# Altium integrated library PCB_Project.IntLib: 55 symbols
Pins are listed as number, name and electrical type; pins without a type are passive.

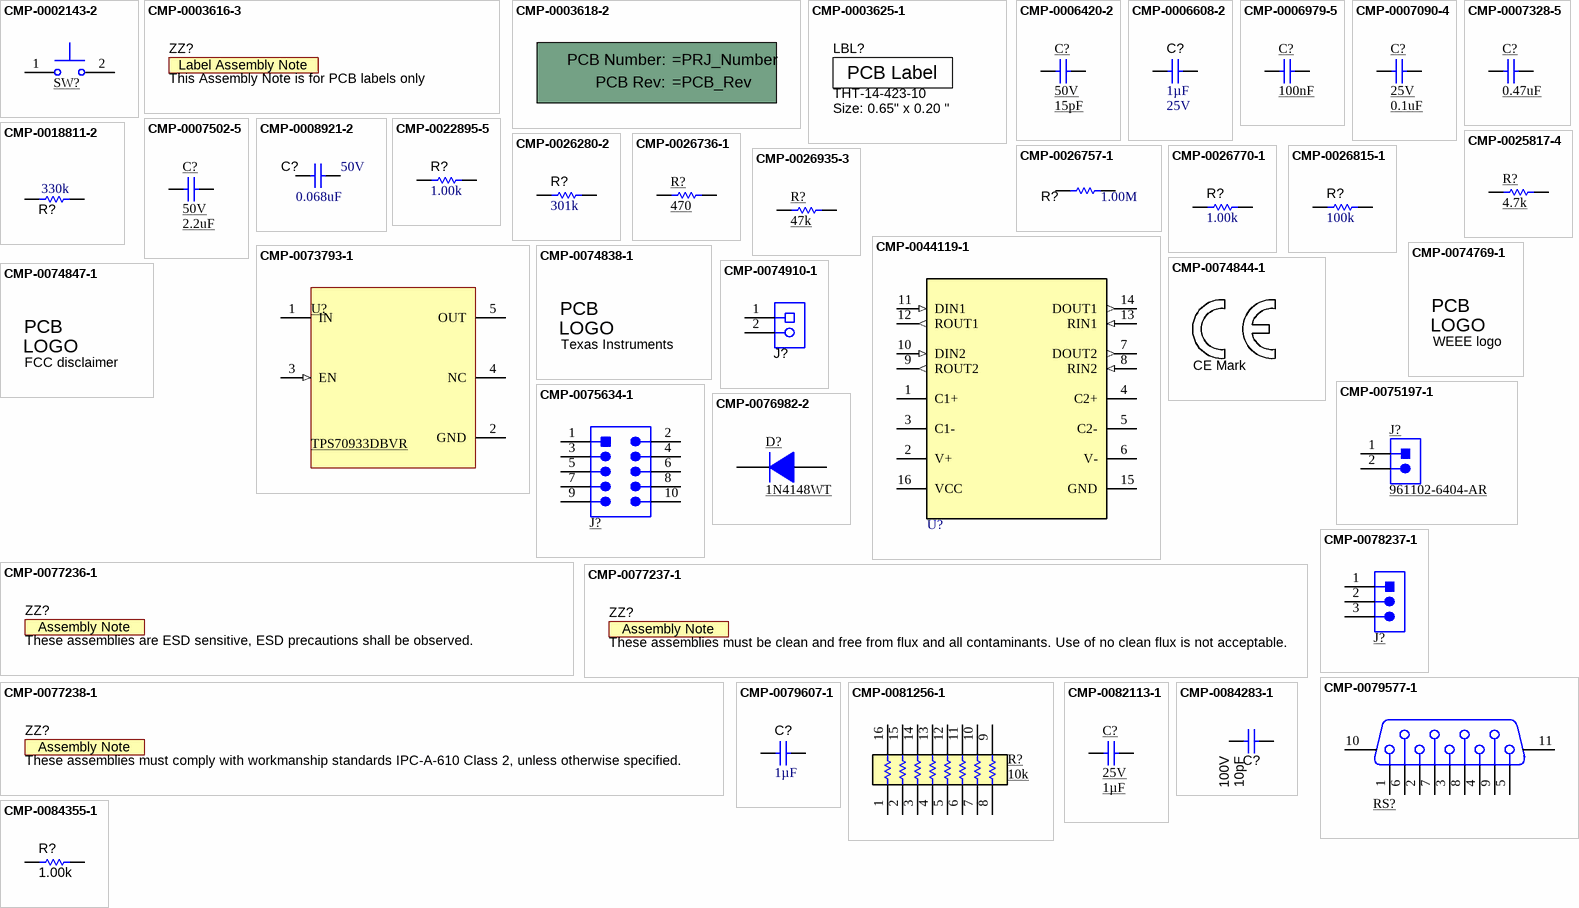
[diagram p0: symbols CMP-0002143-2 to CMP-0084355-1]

## CMP-0002143-2
designator SW?, comment TL1015AF160QG  (value not drawn)
Switch, Tactile, SPST-NO, 0.05A, 12V, SMT; Manufacturer: E-Switch; CurrentRating_mA: 50A; PositionCount: 1; SwitchFunction: Off-Mom
footprint SW_TL1015AF160QG (E-Switch)
pins: 1, 2

## CMP-0003616-3
designator ZZ?, comment This Assembly Note is for PCB labels only  (no BOM)
Key: AssemblyNoteLabel
footprint AssemblyNoteLabel (Assembly Note for PCB Labels)

## CMP-0003618-2
designator !PCB?, comment Printed Circuit Board  (value not drawn)  (mechanical)
Manufacturer: Any; CompType: PCB
1 alternate drawing of the same symbol

## CMP-0003625-1
designator LBL?, comment THT-14-423-10  Note: Size: 0.65" x 0.20 "
Thermal Transfer Printable Labels, 0.650" W x 0.200" H - 10,000 per roll; Manufacturer: Brady; CompType: Label
footprint Label_650x200 (Thermal Transfer Label)

## CMP-0006420-2
designator C?, comment VDC_V: 50V  ValueDisplayed: 15pF  (hidden comment: GRM1555C1H150JA01D)
CAP, CERM, 15 pF, 50 V, +/- 5%, C0G/NP0, 0402; Manufacturer: MuRata; TaMin_C: -55°C; Polarized: N; SizeAreaWB_mm2: 3; Value1: Unknown; U/M: EA; Value: 15pF; TaMax_C: 125°C; SizeZ_mm: 0.6; SizeX_mm: 1; SizeY_mm: 0.5; Cap_Case: 0402; CompType: Capacitor; AEC Category: Q200
footprint 0402 (0402 from SM-752 data)
footprint 0402S (Based on C0402S footprint from PADS legacy)
footprint 0402L (0402 from SM-752 data)
footprint 0402M (0402 from SM-752 data)
pins: 1, 2

## CMP-0006608-2
designator C?, comment Cap_F: 1µF  VDC_V: 25V  (hidden comment: GRM155R61E105KA12D)
CAP, CERM, 1 uF, 25 V, +/- 10%, X5R, 0402; Manufacturer: MuRata; TaMin_C: -55°C; Polarized: N; SizeAreaWB_mm2: 3; U/M: EA; Value: 1uF; TaMax_C: 85°C; SizeZ_mm: 0.6; SizeX_mm: 1; SizeY_mm: 0.5; Cap_Case: 0402; CompType: Capacitor; AEC Category: Q200; Value1: Unknown
footprint 0402 (0402 from SM-752 data)
footprint 0402S (Based on C0402S footprint from PADS legacy)
footprint 0402L (0402 from SM-752 data)
footprint 0402M (0402 from SM-752 data)
pins: 1, 2

## CMP-0006979-5
designator C?, comment Cap_F: 100nF  (hidden comment: C0603X104K3RACTU)
CAP, CERM, 0.1 uF, 25 V, +/- 10%, X7R, 0603; Manufacturer: Kemet; TaMin_C: -55°C; Polarized: N; SizeAreaWB_mm2: 4.68; Value1: Unknown; U/M: EA; Value: 0.1uF; TaMax_C: 125°C; SizeZ_mm: 1; SizeX_mm: 1.6; SizeY_mm: 0.8; Cap_Case: 0603; Value2: 25V; SizeArea_mm2: 1.28; CompType: Capacitor; AEC Category: Q200
footprint 0603 (0603 from SM-752 data)
footprint 0603_HV (Ernesto recommended land pattern.  26 mil between pads.)
footprint 0603L (0603 from SM-752 data)
footprint 0603S
footprint 0603M (0603 from SM-752 data)
pins: 1, 2

## CMP-0007090-4
designator C?, comment VDC_V: 25V  ValueDisplayed: 0.1uF  (hidden comment: CGA3E2X8R1E104K080AA)
CAP, CERM, 0.1 uF, 25 V, +/- 10%, X8R, AEC-Q200 Grade 0, 0603; Manufacturer: TDK; TaMin_C: -55°C; Polarized: N; SizeAreaWB_mm2: 4.68; Value1: Unknown; U/M: EA; Value: 0.1uF; TaMax_C: 150°C; SizeZ_mm: 1; SizeX_mm: 1.6; SizeY_mm: 0.8; Cap_Case: 0603; SizeArea_mm2: 1.28; CompType: Capacitor; AEC Qualified: Y; Cap_F: 100nF; AEC Grade: 0; AEC Category: Q200
footprint 0603 (0603 from SM-752 data)
footprint 0603_HV (Ernesto recommended land pattern.  26 mil between pads.)
footprint 0603L (0603 from SM-752 data)
footprint 0603S
footprint 0603M (0603 from SM-752 data)
pins: 1, 2

## CMP-0007328-5
designator C?, comment ValueDisplayed: 0.47uF  (hidden comment: GRM188R61A474KA61D)
CAP, CERM, 0.47 uF, 10 V, +/- 10%, X5R, 0603; Manufacturer: MuRata; TaMin_C: -55°C; Polarized: N; SizeAreaWB_mm2: 4.68; Value1: Unknown; U/M: EA; Value: 0.47uF; TaMax_C: 85°C; SizeZ_mm: 1; SizeX_mm: 1.6; SizeY_mm: 0.8; Cap_Case: 0603; Value2: 10V; SizeArea_mm2: 1.28; CompType: Capacitor; Cap_F: 470nF; AEC Category: Q200
footprint 0603 (0603 from SM-752 data)
footprint 0603_HV (Ernesto recommended land pattern.  26 mil between pads.)
footprint 0603L (0603 from SM-752 data)
footprint 0603S
footprint 0603M (0603 from SM-752 data)
pins: 1, 2

## CMP-0007502-5
designator C?, comment VDC_V: 50V  ValueDisplayed: 2.2uF  (hidden comment: GRT188R61H225KE13D)
CAP, CERM, 2.2 uF, 50 V, +/- 10%, X5R, AEC-Q200 Grade 3, 0603; Manufacturer: MuRata; TaMin_C: -55°C; Polarized: N; SizeAreaWB_mm2: 4.68; Value1: Unknown; U/M: EA; Value: 2.2uF; TaMax_C: 85°C; SizeZ_mm: 1; SizeX_mm: 1.6; SizeY_mm: 0.8; Cap_Case: 0603; SizeArea_mm2: 1.28; CompType: Capacitor; AEC Qualified: Y; Cap_F: 2.2µF; AEC Grade: 3; AEC Category: Q200
footprint 0603 (0603 from SM-752 data)
footprint 0603_HV (Ernesto recommended land pattern.  26 mil between pads.)
footprint 0603L (0603 from SM-752 data)
footprint 0603S
footprint 0603M (0603 from SM-752 data)
pins: 1, 2

## CMP-0008921-2
designator C?, comment VDC_V: 50V  ValueDisplayed: 0.068uF  (hidden comment: GRM31C5C1H683JA01L)
CAP, CERM, 0.068 uF, 50 V, +/- 5%, C0G/NP0, 1206; Manufacturer: MuRata; TaMin_C: -55°C; ESR_ohm: 10m; Polarized: N; SizeAreaWB_mm2: 10.92; Value1: 0.01 ohm; U/M: EA; TaMax_C: 125°C; SizeZ_mm: 1.8; SizeX_mm: 3.2; SizeY_mm: 1.6; Cap_Case: 1206; SizeArea_mm2: 5.12; CompType: Capacitor; Cap_F: 68nF; IRMS_A: 900mA; AEC Category: Q200
footprint 1206_180
footprint 1206_180L (1206_180)
footprint 1206_180M (1206_180)
pins: 1, 2

## CMP-0018811-2
designator R?, comment ValueDisplayed: 330k  (hidden comment: TNPV1206330KBEEN)
RES, 330 k, 0.1%, 1 W, 1206; Manufacturer: Vishay Draloric; Power_W: 1W; TempCo: 25 ppm/C; U/M: EA; Value: 330k; SizeX_mm: 3.2; SizeY_mm: 1.6; SizeZ_mm: 0.65; SizeArea_mm2: 5.12; CompType: Resistor; AEC Qualified: N; VDC_V: 700V; AEC Category: Q200
footprint TNPV1206 (VISHAY)
pins: 1, 2

## CMP-0022895-5
designator R?, comment ValueDisplayed: 1.00k  (hidden comment: RC0603FR-071KL)
RES, 1.00 k, 1%, 0.1 W, 0603; Manufacturer: Yageo; Power_W: 100mW; TempCo: 100 ppm/C; Value_Code: 1k00; Value: 1.00k; EIA_Code: E96; Res_ohm: 1k; SizeX_mm: 1.6; SizeY_mm: 0.8; SizeZ_mm: 1; Value2: 0.1W; SizeArea_mm2: 1.28; CompType: Resistor; AEC Qualified: N; VDC_V: 75V; AEC Category: Q200; SizeAreaWB_mm2: 4.68
footprint 0603 (0603 from SM-752 data)
footprint 0603_HV (Ernesto recommended land pattern.  26 mil between pads.)
footprint 0603L (0603 from SM-752 data)
footprint 0603S
footprint 0603M (0603 from SM-752 data)
pins: 1, 2

## CMP-0025817-4
designator R?, comment ValueDisplayed: 4.7k  (hidden comment: CRCW06034K70JNEA)
RES, 4.7 k, 5%, 0.1 W, AEC-Q200 Grade 0, 0603; Manufacturer: Vishay-Dale; Power_W: 100mW; TempCo: 200 ppm/C; Value_Code: 4k70; Value: 4.7k; EIA_Code: E24; SizeX_mm: 1.6; SizeY_mm: 0.8; SizeZ_mm: 1; Value2: 0.1W; SizeArea_mm2: 1.28; CompType: Resistor; AEC Qualified: Y; VDC_V: 75V; AEC Category: Q200; AEC Grade: 0
footprint 0603 (0603 from SM-752 data)
footprint 0603_HV (Ernesto recommended land pattern.  26 mil between pads.)
footprint 0603L (0603 from SM-752 data)
footprint 0603S
footprint 0603M (0603 from SM-752 data)
pins: 1, 2

## CMP-0026280-2
designator R?, comment ValueDisplayed: 301k  (hidden comment: CRCW0402301KFKED)
RES, 301 k, 1%, 0.063 W, AEC-Q200 Grade 0, 0402; Manufacturer: Vishay-Dale; Power_W: 63mW; TempCo: 100 ppm/C; Value: 301k; EIA_Code: E96; SizeX_mm: 1; SizeY_mm: 0.5; SizeZ_mm: 0.6; Value2: 0.063W; CompType: Resistor; AEC Qualified: Y; VDC_V: 50V; AEC Category: Q200; AEC Grade: 0
footprint 0402 (0402 from SM-752 data)
footprint 0402S (Based on C0402S footprint from PADS legacy)
footprint 0402L (0402 from SM-752 data)
footprint 0402M (0402 from SM-752 data)
pins: 1, 2

## CMP-0026736-1
designator R?, comment ValueDisplayed: 470  (hidden comment: RC0402FR-07470RL)
RES, 470, 1%, 0.063 W, 0402; Manufacturer: Yageo America; Power_W: 63mW; TempCo: 100 ppm/C; Value_Code: 470R; U/M: EA; Value: 470; SizeX_mm: 1; SizeY_mm: 0.5; SizeZ_mm: 0.6; Value2: 0.063W; CompType: Resistor; AEC Qualified: N; VDC_V: 50V; AEC Category: Q200
footprint 0402 (0402 from SM-752 data)
footprint 0402S (Based on C0402S footprint from PADS legacy)
footprint 0402L (0402 from SM-752 data)
footprint 0402M (0402 from SM-752 data)
pins: 1, 2

## CMP-0026757-1
designator R?, comment ValueDisplayed: 1.00M  (hidden comment: RMCF0402FT1M00)
RES, 1.00 M, 1%, 0.063 W, AEC-Q200 Grade 0, 0402; Manufacturer: Stackpole Electronics Inc; Power_W: 63mW; TempCo: 100 ppm/C; Value_Code: 1M00; Value: 1.00Meg; EIA_Code: E96; Res_ohm: 1M; SizeX_mm: 1; SizeY_mm: 0.5; SizeZ_mm: 0.6; Value2: 0.063W; CompType: Resistor; AEC Qualified: Y; VDC_V: 50V; AEC Category: Q200; AEC Grade: 0; U/M: EA
footprint 0402 (0402 from SM-752 data)
footprint 0402S (Based on C0402S footprint from PADS legacy)
footprint 0402L (0402 from SM-752 data)
footprint 0402M (0402 from SM-752 data)
pins: 1, 2

## CMP-0026770-1
designator R?, comment ValueDisplayed: 1.00k  (hidden comment: ERA-2AEB102X)
RES, 1.00 k, 0.1%, 0.063 W, 0402; Manufacturer: Panasonic; Power_W: 63mW; TempCo: 25 ppm/C; Value_Code: 1k00; Value: 1.00k; EIA_Code: E192; Res_ohm: 1k; SizeX_mm: 1; SizeY_mm: 0.5; SizeZ_mm: 0.6; Value2: 0.063W; CompType: Resistor; AEC Category: Q200; VDC_V: 50V; U/M: EA
footprint 0402 (0402 from SM-752 data)
footprint 0402S (Based on C0402S footprint from PADS legacy)
footprint 0402L (0402 from SM-752 data)
footprint 0402M (0402 from SM-752 data)
pins: 1, 2

## CMP-0026815-1
designator R?, comment ValueDisplayed: 100k  (hidden comment: RG1005P-104-B-T5)
RES, 100 k, 0.1%, 0.063 W, 0402; Manufacturer: Susumu Co Ltd; Power_W: 63mW; TempCo: 25 ppm/C; Value: 100k; EIA_Code: E192; SizeX_mm: 1; SizeY_mm: 0.5; SizeZ_mm: 0.6; Value2: 0.063W; CompType: Resistor; AEC Category: Q200; U/M: EA
footprint 0402 (0402 from SM-752 data)
footprint 0402S (Based on C0402S footprint from PADS legacy)
footprint 0402L (0402 from SM-752 data)
footprint 0402M (0402 from SM-752 data)
pins: 1, 2

## CMP-0026935-3
designator R?, comment ValueDisplayed: 47k  (hidden comment: CRCW040247K0JNED)
RES, 47 k, 5%, 0.063 W, AEC-Q200 Grade 0, 0402; Manufacturer: Vishay-Dale; Power_W: 63mW; TempCo: 200 ppm/C; Value_Code: 47k0; Value: 47k; EIA_Code: E24; SizeX_mm: 1; SizeY_mm: 0.5; SizeZ_mm: 0.6; Value2: 0.063W; CompType: Resistor; AEC Qualified: Y; VDC_V: 50V; AEC Category: Q200; AEC Grade: 0
footprint 0402 (0402 from SM-752 data)
footprint 0402S (Based on C0402S footprint from PADS legacy)
footprint 0402L (0402 from SM-752 data)
footprint 0402M (0402 from SM-752 data)
pins: 1, 2

## CMP-0044119-1
designator U?, comment TRS3232EIDBR  (value not drawn)
3-V to 5.5-V Multichannel RS-232 Line Driver / Receiver with ±15-kV IEC ESD Protection, -40 to 85 degC, 16-Pin SSOP (DB), Green (RoHS & no Sb/Br); ESD HBM(kV): +/-15; Receivers Per Package: 2; Single Supply: TRUE; ICC(Max)(mA): 1; Supply Voltage(s)(V): 3.3 or 5.0
footprint DB0016A_L (SOP, 16-Leads, Body 6.2x5.3mm, Pitch 0.65mm, IPC High Density)
footprint DB0016A_M (SOP, 16-Leads, Body 6.2x5.3mm, Pitch 0.65mm, IPC Low Density)
footprint DB0016A_N (SOP, 16-Leads, Body 6.2x5.3mm, Pitch 0.65mm, IPC Medium Density)
pins: 1 C1+, 2 V+ (power), 3 C1-, 4 C2+, 5 C2-, 6 V- (power), 7 DOUT2 (out), 8 RIN2 (in), 9 ROUT2 (out), 10 DIN2 (in), 11 DIN1 (in), 12 ROUT1 (out), 13 RIN1 (in), 14 DOUT1 (out), 15 GND (power), 16 VCC (power)

## CMP-0073793-1
designator U?, comment TPS70933DBVR
150-mA, 30-V, Ultra-Low IQ, Wide Input Low-Dropout Regulator with Reverse Current Protection, DBV0005A (SOT-23-5); Alternate PartNumber: TPS70933DBVT; Alternate Manufacturer: Texas Instruments; Green_Lifecycle: Active; SizeAreaWB_mm2: 14.82; Green_REACh: Passed; U/M: EA; SizeZ_mm: 1.45; SizeX_mm: 2.8; SizeY_mm: 2.9; SizeArea_mm2: 8.12; CompType: IC
footprint DBV0005A_N (SOT23, 5-Leads, Body 2.9x1.6mm, Pitch 0.95mm, Lead Span 2.8mm, IPC Medium Density)
footprint DBV0005A_L (SOT23, 5-Leads, Body 2.9x1.6mm, Pitch 0.95mm, Lead Span 2.8mm, IPC High Density)
footprint DBV0005A_M (SOT23, 5-Leads, Body 2.9x1.6mm, Pitch 0.95mm, Lead Span 2.8mm, IPC Low Density)
pins: 1 IN (power) "Unregulated input to the device", 2 GND (power) "Ground", 3 EN (in) "Enable pin", 4 NC "No internal connection", 5 OUT (power) "Regulated output voltage."
1 alternate drawing of the same symbol

## CMP-0074769-1
designator Logo?, comment WEEE logo  (no BOM)
footprint WEEE_Minimum (WEEElie bin)

## CMP-0074838-1
designator Logo?, comment Texas Instruments  (no BOM)
Texas Instrument Corporate Signature; SymbolCreator: a0412235; Lib Reference: TI_Logo; Library Reference: Logo
footprint TI_Horizontal_Overlay_Medium
footprint TI_Horizontal_Overlay_Small
footprint TI_Stacked_SolderMask_Small
footprint TI_Stacked_SolderMask_Small_Vertical
footprint TI_Symbol_Overlay_Medium
footprint TI_Symbol_Overlay_Small
footprint TI_Symbol_SolderMask_Medium
footprint TI_Symbol_SolderMask_Small
footprint TI_Horizontal_SolderMask_Medium
footprint TI_Horizontal_SolderMask_Small
footprint TI_Stacked_Overlay_Medium
footprint TI_Stacked_Overlay_Medium_Vertical
footprint TI_Stacked_Overlay_Small
footprint TI_Stacked_Overlay_Small_Vertical
footprint TI_Stacked_SolderMask_Medium
footprint TI_Stacked_SolderMask_Medium_Vertical

## CMP-0074844-1
designator Logo?, comment CE Mark  (no BOM)
SymbolCreator: a0412235
footprint CE_Mark_5mm (Minimum text height for CE Mark)
footprint CE_Mark_10mm (Double the minimum text height for CE Mark)

## CMP-0074847-1
designator Logo?, comment FCC disclaimer  (no BOM)
FCC_disclaimer; Library Reference: Logo
footprint FCC_disclaimer
footprint FCC_disclaimer_stacked

## CMP-0074910-1
designator J?, comment ED120/2DS  (value not drawn)
Terminal Block, 5.08 mm, 2x1, Brass, TH; Manufacturer: On-Shore Technology; Cert_VDE: Y; CNHeader: False; Current_A: 15A; Green_Lifecycle: Not Set; Shrouded: N; Gender: Female; Green_REACh: Incomplete; Voltage_V: 300V; Row_Count: 1; Pitch_mm: 5.08; CT: True
footprint On-Shore_ED120_2DS (ONSHORE)
pins: 1, 2

## CMP-0075197-1
designator J?, comment 961102-6404-AR
Header, 2.54mm, 2x1, TH; Manufacturer: 3M; CNHeader: True; Current_A: 2A; Green_Lifecycle: Active; Shrouded: N; Gender: Male; Green_REACh: Passed; Voltage_V: 1kV; Row_Count: 1; Pitch_mm: 2.54; ContactFinish: Gold; CT: False; Cert_UL: Y
footprint 3M_961102-6404-AR (Header, 2.54mm, 2x1, TH)
pins: 1, 2
1 alternate drawing of the same symbol

## CMP-0075634-1
designator J?, comment FTSH-105-01-L-DV-K  (value not drawn)
Header(Shrouded), 1.27mm, 5x2, Gold, SMT; Manufacturer: Samtec; Pitch_mm: 1.27; Gender: Male; Cert_CSA: Y; Current_A: 3.3A; CT: False; Row_Count: 2
footprint Samtec_FTSH-105-01-x-DV-K (Header(Shrouded), 1.27mm, 5x2, SMT)
pins: 1, 2, 3, 4, 5, 6, 7, 8, 9, 10

## CMP-0076982-2
designator D?, comment 1N4148WT
Diode, Switching, 75 V, 0.3 A, SOD-523F; Manufacturer: Fairchild Semiconductor; TJmax_C: 150°C; AEC Category: Q101; SizeX_mm: 1.6; Value: 75V; Io_A: 300mA; Value1: 0.3A; Green_REACh: Incomplete; SizeZ_mm: 0.7; Green_Lifecycle: Not Set; SizeArea_mm2: 1.28; SizeAreaWB_mm2: 4.68; SizeY_mm: 0.8
footprint Fairchild_SOD-523F (SMD, 2-Leads, Body 1.2x0.8mm)
pins: 1 K, 2 A

## CMP-0077236-1
designator ZZ?, comment These assemblies are ESD sensitive, ESD precautions shall be observed.  (no BOM)
CompType: AssemblyNote
footprint AssemblyNote (Assembly Note)

## CMP-0077237-1
designator ZZ?, comment These assemblies must be clean and free from flux and all contaminants. Use of no clean flux is not acceptable.  (no BOM)
CompType: AssemblyNote
footprint AssemblyNote (Assembly Note)

## CMP-0077238-1
designator ZZ?, comment These assemblies must comply with workmanship standards IPC-A-610 Class 2, unless otherwise specified.  (no BOM)
CompType: AssemblyNote
footprint AssemblyNote (Assembly Note)

## CMP-0078237-1
designator J?, comment 22284030  (value not drawn)
Header, 2.54mm, 3x1, Tin, TH; Manufacturer: Molex; Pitch_mm: 2.54; Gender: Male; Cert_CSA: Y; Current_A: 4A; Voltage_V: 500V; Shrouded: N; Row_Count: 1
footprint Molex_0022284030 (Header, 2.54mm, 3x1, Tin, TH)
pins: 1, 2, 3
3 alternate drawings of the same symbol

## CMP-0079577-1
designator RS?, comment 2-5747706-0  (value not drawn)
Receptacle, D-SUB-9, 2.74mm, Gold, TH; Manufacturer: TE Connectivity; Gender: Female; Cert_UL: Y; Voltage_V: 125V; Current_A: 6A; Row_Count: 2; CompType: D-Sub
footprint TE_2-5747706-0 (Receptacle, D-SUB-9, 2.74mm, TH)
pins: 1, 2, 3, 4, 5, 6, 7, 8, 9, 10, 11

## CMP-0079607-1
designator C?, comment Cap_F: 1µF  (hidden comment: CGA3E1X7R1C105K080AC)
CAP, CERM, 1 µF, 16 V,+/- 10%, X7R, AEC-Q200 Grade 1, 0603; Manufacturer: TDK; TaMin_C: -55°C; Polarized: N; SizeAreaWB_mm2: 4.68; U/M: EA; Value: 1uF; TaMax_C: 125°C; SizeZ_mm: 1; SizeX_mm: 1.6; SizeY_mm: 0.8; Cap_Case: 0603; Value2: 16V; SizeArea_mm2: 1.28; CompType: Capacitor; AEC Qualified: Y; AEC Category: Q200
footprint 0603 (0603 from SM-752 data)
footprint 0603M (0603 from SM-752 data)
footprint 0603L (0603 from SM-752 data)
footprint 0603_HV (Ernesto recommended land pattern.  26 mil between pads.)
footprint 0603S
pins: 1, 2

## CMP-0081256-1
designator R?, comment ValueDisplayed: 10k  (hidden comment: EXB2HV103JV)
RES, 10 k, 5%, 0.063 W, AEC-Q200 Grade 1, Resistor Array - 8x1; Manufacturer: Panasonic; Value_Code: 10k0; AEC Qualified: Y; AEC Category: Q200; Value: 10k; EIA_Code: E24; TempCo: 200 ppm/C; AEC Grade: 1; Power_W: 63mW; VDC_V: 25V; Value2: 0.063W
footprint RESCAXS_EXB-2HV (Panasonic Resistor Array)
pins: 1, 2, 3, 4, 5, 6, 7, 8, 9, 10, 11, 12, 13, 14, 15, 16

## CMP-0082113-1
designator C?, comment VDC_V: 25V  ValueDisplayed: 1µF  (hidden comment: CGA3E1X7R1E105M080AC)
CAP, CERM, 1 µF, 25 V,+/- 20%, X7R, AEC-Q200 Grade 1, 0603; Manufacturer: TDK; SizeAreaWB_mm2: 4.68; SizeArea_mm2: 1.28; AEC Qualified: Y; AEC Category: Q200; Value: 1uF; TaMax_C: 125°C; SizeZ_mm: 1; Polarized: N; TaMin_C: -55°C; SizeY_mm: 0.8; U/M: EA; CompType: Capacitor; SizeX_mm: 1.6; Cap_Case: 0603
footprint 0603 (0603 from SM-752 data)
footprint 0603M (0603 from SM-752 data)
footprint 0603L (0603 from SM-752 data)
footprint 0603_HV (Ernesto recommended land pattern.  26 mil between pads.)
footprint 0603S
pins: 1, 2

## CMP-0084283-1
designator C?, comment ValueDisplayed: 10pF  VDC_V: 100V  (hidden comment: GCM1885C2A100JA16D)
CAP, CERM, 10 pF, 100 V,+/- 5%, C0G/NP0, AEC-Q200 Grade 1, 0603; Manufacturer: MuRata; TaMax_C: 125°C; Cap_Case: 0603; SizeX_mm: 1.6; SizeY_mm: 0.8; SizeArea_mm2: 1.28; CompType: Capacitor; Polarized: N; AEC Category: Q200; SizeAreaWB_mm2: 4.68; AEC Qualified: Y; SizeZ_mm: 1; Value: 10pF; U/M: EA; TaMin_C: -55°C
footprint 0603 (0603 from SM-752 data)
footprint 0603M (0603 from SM-752 data)
footprint 0603L (0603 from SM-752 data)
footprint 0603_HV (Ernesto recommended land pattern.  26 mil between pads.)
footprint 0603S
pins: 1, 2

## CMP-0084355-1
designator R?, comment ValueDisplayed: 1.00k  (hidden comment: RT0603DRD071KL)
RES, 1.00 k, 0.5%, 0.1 W, 0603; Manufacturer: Yageo; SizeArea_mm2: 1.28; Value2: 0.1W; Res_ohm: 1k; Power_W: 100mW; EIA_Code: E192; SizeAreaWB_mm2: 4.68; TempCo: 25 ppm/C; SizeY_mm: 0.8; SizeX_mm: 1.6; AEC Qualified: N; Value_Code: 1k00; CompType: Resistor; SizeZ_mm: 1; AEC Category: Q200; Value: 1.00k
footprint 0603 (0603 from SM-752 data)
footprint 0603M (0603 from SM-752 data)
footprint 0603L (0603 from SM-752 data)
footprint 0603_HV (Ernesto recommended land pattern.  26 mil between pads.)
footprint 0603S
pins: 1, 2

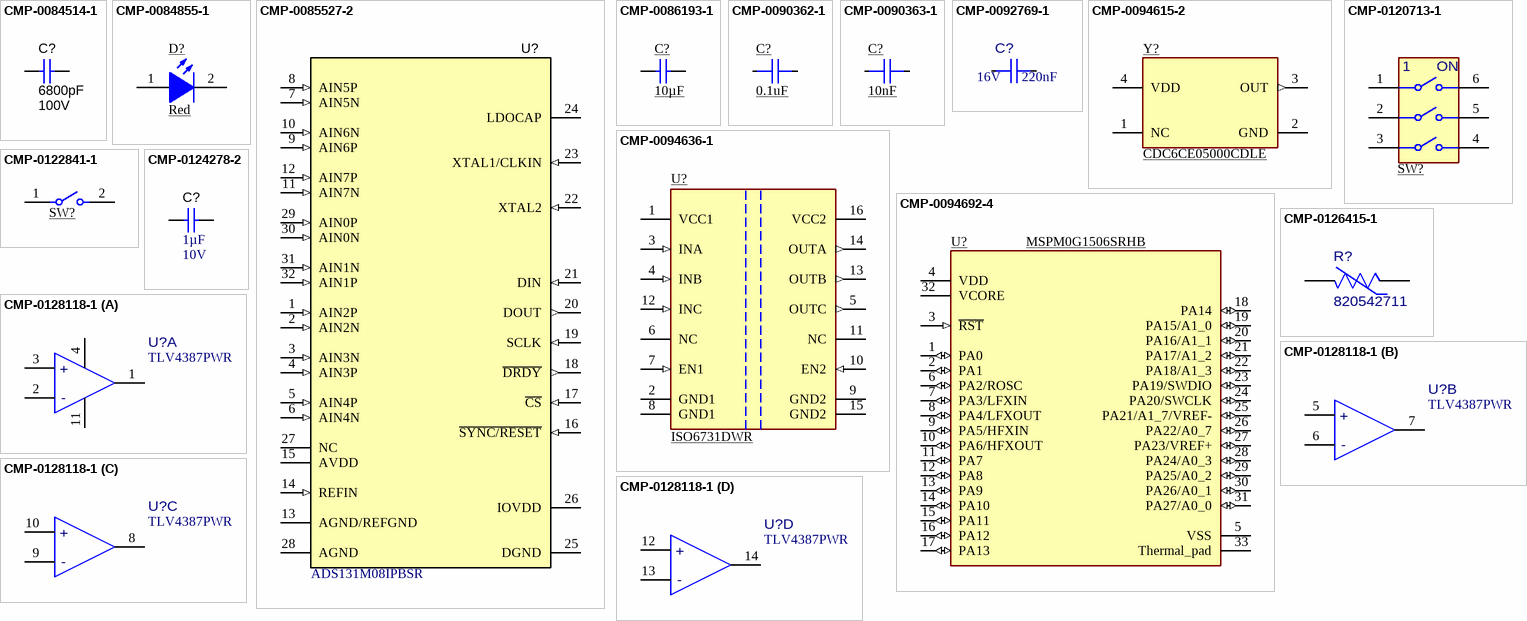
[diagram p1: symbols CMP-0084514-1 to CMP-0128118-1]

## CMP-0084514-1
designator C?, comment ValueDisplayed: 6800pF  VDC_V: 100V  (hidden comment: CGA3EANP02A682J080AC)
CAP, CERM, 6800 pF, 100 V,+/- 5%, C0G/NP0, AEC-Q200 Grade 0, 0603; Manufacturer: TDK; U/M: EA; SizeAreaWB_mm2: 4.68; Value: 6800pF; Polarized: N; AEC Qualified: Y; TaMax_C: 150°C; AEC Grade: 0; SizeX_mm: 1.6; Cap_F: 6.8nF; TaMin_C: -55°C; Cap_Case: 0603; CompType: Capacitor; SizeZ_mm: 1; SizeY_mm: 0.8; AEC Category: Q200; SizeArea_mm2: 1.28
footprint 0603 (0603 from SM-752 data)
footprint 0603M (0603 from SM-752 data)
footprint 0603L (0603 from SM-752 data)
footprint 0603_HV (Ernesto recommended land pattern.  26 mil between pads.)
footprint 0603S
pins: 1, 2

## CMP-0084855-1
designator D?, comment value Red  (hidden comment: CMD17-21SRC/TR8)
LED, Red, SMD; Manufacturer: Visual Communications Company, LLC; SizeX_mm: 2; SizeArea_mm2: 2.5; SizeAreaWB_mm2: 6.75; Angle: 140; Value2: 1.7V; Ir_A: 100µA; Value1: 0.1W; SizeY_mm: 1.25; Io_A: 20mA; Tjmax_C: 85°C; Power_TotalModule: 100mW; SizeZ_mm: 1.2; Vr_V: 5V
footprint CMD17-21_Red (SMD, 2-Leads, Body 2x1.25mm)
pins: 1 A, 2 K

## CMP-0085527-2
designator U?, comment ADS131M08IPBSR
8-Channel, 24-Bit, Simultaneously-Sampling, Delta-Sigma ADC, PBS0032A (TQFP-32); Manufacturer: Texas Instruments; SizeZ_mm: 1.2; AEC Qualified: N; SizeArea_mm2: 49; SizeAreaWB_mm2: 81; CompType: IC; SizeX_mm: 7; AEC Category: Q200
footprint PBS0032A_N
footprint PBS0032A_M
footprint PBS0032A_L
pins: 1 AIN2P (in), 2 AIN2N (in), 3 AIN3N (in), 4 AIN3P (in), 5 AIN4P (in), 6 AIN4N (in), 7 AIN5N (in), 8 AIN5P (in), 9 AIN6P (in), 10 AIN6N (in), 11 AIN7N (in), 12 AIN7P (in), 13 AGND/REFGND (power), 14 REFIN (in), 15 AVDD (power), 16 ~{SYNC/RESET} (in), 17 ~{CS} (in), 18 ~{DRDY} (out), 19 SCLK (in), 20 DOUT (out), 21 DIN (in), 22 XTAL2 (in), 23 XTAL1/CLKIN (in), 24 LDOCAP, 25 DGND (power), 26 IOVDD (power), 27 NC, 28 AGND (power), 29 AIN0P (in), 30 AIN0N (in), 31 AIN1N (in), 32 AIN1P (in)

## CMP-0086193-1
designator C?, comment ValueDisplayed: 10µF  (hidden comment: GRM188R61A106KAALD)
CAP, CERM, 10 µF, 10 V,+/- 10%, X5R, 0603; Manufacturer: MuRata; SizeArea_mm2: 1.28; SizeY_mm: 0.8; TaMax_C: 85°C; TaMin_C: -55°C; VDC_V: 10V; Polarized: N; SizeAreaWB_mm2: 4.68; SizeZ_mm: 1; SizeX_mm: 1.6; AEC Category: Q200; CompType: Capacitor; Cap_Case: 0603; U/M: EA; Value: 10uF
footprint 0603 (0603 from SM-752 data)
footprint 0603M (0603 from SM-752 data)
footprint 0603L (0603 from SM-752 data)
footprint 0603_HV (Ernesto recommended land pattern.  26 mil between pads.)
footprint 0603S
pins: 1, 2

## CMP-0090362-1
designator C?, comment ValueDisplayed: 0.1uF  (hidden comment: 885012205018)
0.1µF ±10% 10V Ceramic Capacitor X7R 0402 (1005 Metric); Manufacturer: Wurth Electronics; AEC Qualified: No; Value: 100nF; SizeZ_mm: 0.55mm; TempCo: 15%
footprint FP-885012205018_0402-MFG
footprint FP-885012205018_0402-IPC_C
footprint FP-885012205018_0402-IPC_B
footprint FP-885012205018_0402-IPC_A
pins: 1, 2

## CMP-0090363-1
designator C?, comment ValueDisplayed: 10nF  (hidden comment: 885012205050)
10000pF ±10% 25V Ceramic Capacitor X7R 0402 (1005 Metric); Manufacturer: Wurth Electronics; SizeZ_mm: 0.55mm; AEC Qualified: No; Value: 10nF; TempCo: 15%
footprint FP-885012205050_0402-MFG
footprint FP-885012205050_0402-IPC_C
footprint FP-885012205050_0402-IPC_B
footprint FP-885012205050_0402-IPC_A
pins: 1, 2

## CMP-0092769-1
designator C?, comment ValueDisplayed: 220nF  VDC_V: 16V  (hidden comment: CGA2B2X7R1C224K050BE)
Cap Ceramic 220nF 16V X7R 10% Pad SMD 0402 +125°C Automotive T/R; Manufacturer: TDK Corporation; Tolerance_%: 0.1%; AEC Qualified: Yes; AEC Grade: Grade 1; TempCo: 15%; SizeZ_mm: 0.55mm
footprint FP-CGA2B2X7R1C224K050BE_0402-MFG
footprint FP-CGA2B2X7R1C224K050BE_0402-IPC_C
footprint FP-CGA2B2X7R1C224K050BE_0402-IPC_B
footprint FP-CGA2B2X7R1C224K050BE_0402-IPC_A
pins: 1, 2

## CMP-0094615-2
designator Y?, comment PartNumber: CDC6CE05000CDLE  (hidden comment: CDC6CE008192ADLE)
Crystal replacement: Ultra-low Power LVCMOS Oscillator 4-pin, VSON 3.2 x 2.5 x 0.9mm; Manufacturer: Texas Instruments; AEC Qualified: No; Standoff Height: 0mm; Min Supply Voltage: 2.375V; TaMin_C: -40°C; Load Capacitance: 15pF; Frequency Stability: 20ppm; AEC Category: Q200; Frequency_Fixed: 50MHz; CompType: IC; SizeZ_mm: 1mm; Max Supply Voltage: 3.465V; TJmax_C: +135°C; TaMax_C: +105°C; Max Supply Current: 4mA
footprint DLE0004A-MFG
pins: 1 NC, 2 GND (power), 3 OUT (out), 4 VDD (power)

## CMP-0094636-1
designator U?, comment ISO6731DWR
Manufacturer: Texas Instruments; Min Supply Voltage: 1.71V; TJmax_C: +150°C; Max Supply Voltage: 5.5V; Standoff Height: 0.1mm; TaMax_C: +125°C; SizeZ_mm: 2.65mm; Interface: SPI,CAN,RS-232,RS-485; TaMin_C: -40°C; AEC Qualified: No
footprint DW0016A-MFG
footprint DW0016A-IPC_C
footprint DW0016A-IPC_B
footprint DW0016A-IPC_A
pins: 1 VCC1 (power), 2 GND1 (power), 3 INA (in), 4 INB (in), 5 OUTC (out), 6 NC, 7 EN1 (in), 8 GND1 (power), 9 GND2 (power), 10 EN2 (in), 11 NC, 12 INC (in), 13 OUTB (out), 14 OUTA (out), 15 GND2 (power), 16 VCC2 (power)

## CMP-0094692-4
designator U?, comment MSPM0G1506SRHB
Mixed-Signal Microcontrollers; Manufacturer: Texas Instruments; Frequency_Fixed: 80MHz; Number Of Timers/Counters: 7; Number Of Cores: 1; AEC Category: Q200; Data Bus Width: 32bits; Standoff Height: 0mm; Memory Type: FLASH; Number Of Uart Channels: 4; Memory Size: 64KBytes; TaMin_C: -40°C; Number Of I2C Channels: 2; Max Supply Voltage: 3.6V; SizeZ_mm: 0.9mm; CompType: IC; Interface: I2C,SPI,UART,LIN,IrDA,SMBus; Min Supply Voltage: 1.35V; AEC Qualified: No; Core Architecture: ARM Cortex-M0+; Number Of Adc Channels: 10; Ram Size: 32KBytes; Number Of I/Os: 28; TaMax_C: +105°C
footprint RHB0032N-MFG
footprint RHB0032N-IPC_C
footprint RHB0032N-IPC_B
footprint RHB0032N-IPC_A
pins: 1 PA0 (io), 2 PA1 (io), 3 ~{RST} (in), 4 VDD (power), 5 VSS (power), 6 PA2/ROSC (io), 7 PA3/LFXIN (io), 8 PA4/LFXOUT (io), 9 PA5/HFXIN (io), 10 PA6/HFXOUT (io), 11 PA7 (io), 12 PA8 (io), 13 PA9 (io), 14 PA10 (io), 15 PA11 (io), 16 PA12 (io), 17 PA13 (io), 18 PA14 (io), 19 PA15/A1_0 (io), 20 PA16/A1_1 (io), 21 PA17/A1_2 (io), 22 PA18/A1_3 (io), 23 PA19/SWDIO (io), 24 PA20/SWCLK (io), 25 PA21/A1_7/VREF- (io), 26 PA22/A0_7 (io), 27 PA23/VREF+ (io), 28 PA24/A0_3 (io), 29 PA25/A0_2 (io), 30 PA26/A0_1 (io), 31 PA27/A0_0 (io), 32 VCORE (power), 33 Thermal_pad (power)

## CMP-0120713-1
designator SW?, comment 416131160803  (value not drawn)
Dip Switch SPST 3 Position Surface Mount Slide (Standard) Actuator 25mA 24VDC; Manufacturer: Wurth Electronics; PositionCount: 3; SizeZ_mm: 2.65mm; VDC_V: 24V; AEC Qualified: No; Coil Resistance_ohm: 100mΩ; Electromechanical Life: 2000Cycles; Standoff Height: 0mm
footprint FP-416131160803_SMT_SW_5MM8_4MM98-MFG
pins: 1, 2, 3, 4, 5, 6

## CMP-0122841-1
designator SW?, comment TDA01H0SB1R  (value not drawn)
Dip Switch SPST 1 Position Surface Mount Slide (Standard) Actuator 25mA 24VDC; Manufacturer: C&K Components; Circuit: SPST-NO; PositionCount: 1; SizeZ_mm: 2.3mm; VDC_V: 24V; AEC Qualified: No; Coil Resistance_ohm: 100mΩ; Electromechanical Life: 1000Cycles; Standoff Height: 0.1mm
footprint FP-TDA01H0SB1R_SMT_SW_2MM40_6MM20-MFG
pins: 1, 2

## CMP-0124278-2
designator C?, comment Cap_F: 1µF  VDC_V: 10V  (hidden comment: KAM05CR71A105MH)
1 µF ±20% 10V Ceramic Capacitor X7R 0402 (1005 Metric); Manufacturer: KYOCERA AVX; TempCo: 15%; Value: 1µF; SizeZ_mm: 0.7mm; AEC Qualified: Yes; AEC Grade: Grade 1; ValueDisplayed: 1uF
footprint FP-KAM05CR71A105MH_0402-MFG (Recommended Land Pattern)
footprint FP-KAM05CR71A105MH_0402-IPC_C
footprint FP-KAM05CR71A105MH_0402-IPC_B
footprint FP-KAM05CR71A105MH_0402-IPC_A
pins: 1, 2

## CMP-0126415-1
designator R?, comment 820542711
430 V 4.5 kA Varistor 1 Circuit Through Hole Disc 14mm; Manufacturer: Wurth Electronics; SizeZ_mm: 20mm; AEC Qualified: No; Cap_F: 450pF; Clamping Voltage: 710V; Varistor Voltage: 430V; VDC_V: 350V; Voltage Tolerance: 10%
footprint FP-820542711_RADIAL-MFG (Recommended Land Pattern)
pins: 1, 2

## CMP-0128118-1
designator U?, comment TLV4387PWR
Quad, ultra-high-precision (10 μV) zero-drift (0.01 μV/°C) low-input-bias-current op amp 14-TSSOP -40 to 125; Manufacturer: Texas Instruments; SizeZ_mm: 1.2mm; AEC Qualified: No; Gain Bandwidth: 5.7MHz; Input Bias Current: 60pA; Input Offset Voltage: 1uV; Max Dual Supply Voltage: 2.75V; Max Supply Voltage: 5.5V; Min Dual Supply Voltage: 850mV; Min Supply Voltage: 1.7V; Number Of Channels: 4; Output Current Per Channel: 55mA; Response Time: 2.5us; Standoff Height: 0.05mm; TaMax_C: +125°C; TaMin_C: -40°C; TJmax_C: +150°C; Voltage Gain: 145dB
footprint PW0014A-MFG (Recommended Land Pattern)
footprint PW0014A-IPC_C
footprint PW0014A-IPC_B
footprint PW0014A-IPC_A
part A pins: 1 OUT_A, 2 -IN_A (hiz), 3 +IN_A (hiz), 4 V+ (power), 11 V- (power)
part B pins: 5 +IN_B (hiz), 6 -IN_B (hiz), 7 OUT_B
part C pins: 8 OUT_C, 9 -IN_C (hiz), 10 +IN_C (hiz)
part D pins: 12 +IN_D (hiz), 13 -IN_D (hiz), 14 OUT_D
